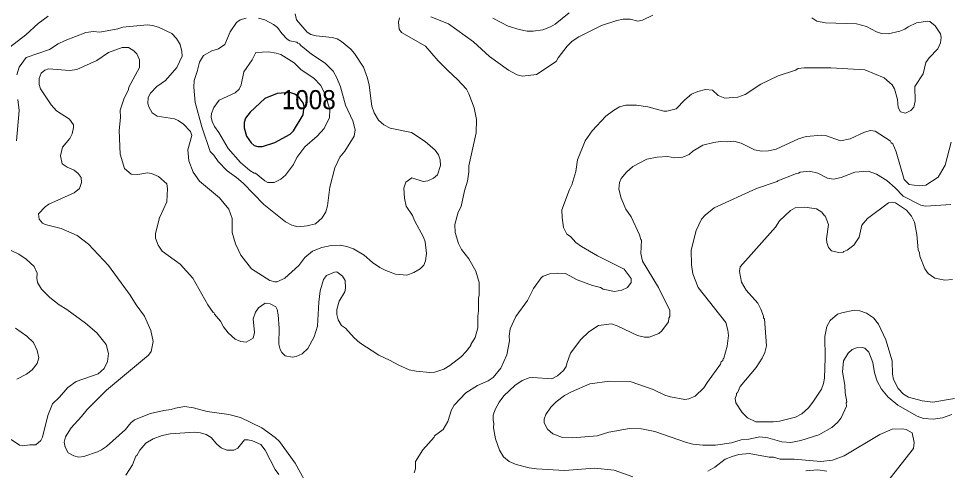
# Model space of a CAD drawing. Extents: x 447.8 to 473.9, y 7733.1 to 7760.8.
# Drawn here: x 456.578 to 460.462, y 7748.586 to 7750.473 of the extents above; entities that cross this region are included whole.
import ezdxf

# ---------------------------------------------------------------- set-up
doc = ezdxf.new("R2010")
doc.units = 0
doc.header["$LTSCALE"] = 0.032
doc.layers.add('1', color=7, linetype='Continuous', lineweight=25)
doc.layers.add('2', color=7, linetype='Continuous', lineweight=13)
doc.layers.add('21', color=7, linetype='Continuous')

msp = doc.modelspace()

# ---------------------------------------------------------------- linework, layer by layer
at = {"layer": '1'}
msp.add_lwpolyline([(457.7136, 7749.9901), (457.7272, 7750.0039), (457.7685, 7750.0716), (457.7728, 7750.1073), (457.7679, 7750.1205), (457.751, 7750.1437), (457.7326, 7750.1574), (457.713, 7750.1645), (457.6597, 7750.1606), (457.6083, 7750.1392), (457.5461, 7750.0824), (457.5274, 7750.0565), (457.5208, 7750.0394), (457.5208, 7750.0167), (457.5316, 7749.9823), (457.5506, 7749.9536), (457.5633, 7749.943), (457.5792, 7749.9394), (457.5975, 7749.9394), (457.6503, 7749.9548)], close=True, dxfattribs=at)
at = {"layer": '2'}
for points in [[(456.523, 7750.3393), (456.608, 7750.4053), (456.6607, 7750.453), (456.7013, 7750.4825)], [(457.7343, 7750.4929), (457.7399, 7750.4672), (457.785, 7750.4162), (457.8007, 7750.4072), (457.8229, 7750.4004), (457.8899, 7750.3947), (457.9101, 7750.3881), (457.9285, 7750.3767), (457.967, 7750.3454), (457.9829, 7750.3271), (458.0208, 7750.2702), (458.0369, 7750.2242), (458.0436, 7750.1945), (458.0549, 7750.1074), (458.0652, 7750.0791), (458.083, 7750.0482), (458.1048, 7750.029), (458.132, 7750.0158), (458.2205, 7749.9971), (458.278, 7749.9592), (458.3194, 7749.9241), (458.3335, 7749.9043), (458.341, 7749.8832), (458.3426, 7749.8596), (458.3297, 7749.8209), (458.3125, 7749.8066), (458.2891, 7749.7958), (458.2702, 7749.7928), (458.2223, 7749.8077), (458.1977, 7749.7895), (458.1896, 7749.7649), (458.1912, 7749.7223), (458.1989, 7749.69), (458.2256, 7749.65), (458.2338, 7749.6297), (458.2712, 7749.5597), (458.2777, 7749.5402), (458.2841, 7749.4921), (458.2801, 7749.4608), (458.272, 7749.4426), (458.2578, 7749.4273), (458.2307, 7749.4121), (458.2022, 7749.4009), (458.1544, 7749.4053), (458.1132, 7749.4201), (458.0884, 7749.4333), (458.0581, 7749.4546), (458.0236, 7749.4848), (457.9789, 7749.5116), (457.9511, 7749.521), (457.9226, 7749.5265), (457.8845, 7749.525), (457.8459, 7749.5162), (457.8067, 7749.5022), (457.7757, 7749.475), (457.75, 7749.4422), (457.6915, 7749.3894), (457.6597, 7749.3735), (457.6497, 7749.3735), (457.6285, 7749.3793), (457.5523, 7749.4273), (457.5071, 7749.4846), (457.4847, 7749.5328), (457.4707, 7749.5796), (457.4713, 7749.638), (457.4575, 7749.6768), (457.4187, 7749.7242), (457.3353, 7749.7933), (457.308, 7749.8317), (457.2902, 7749.8782), (457.2863, 7749.9244), (457.3021, 7749.9852), (457.2964, 7750.0011), (457.2675, 7750.0326), (457.2454, 7750.048), (457.23, 7750.054), (457.1582, 7750.066), (457.1369, 7750.0792), (457.1229, 7750.1039), (457.119, 7750.1184), (457.1194, 7750.144), (457.1294, 7750.1616), (457.1569, 7750.1892), (457.1918, 7750.2147), (457.2395, 7750.2683), (457.262, 7750.3158), (457.2613, 7750.3353), (457.2533, 7750.3642), (457.2386, 7750.3893)], [(458.3022, 7750.4801), (458.3761, 7750.4515), (458.4806, 7750.376), (458.5477, 7750.3152), (458.6263, 7750.2579), (458.663, 7750.2385), (458.6851, 7750.2321), (458.743, 7750.2392), (458.8262, 7750.2935), (458.8343, 7750.3092), (458.8714, 7750.3573), (458.893, 7750.3783), (458.9213, 7750.3972), (459.0149, 7750.4437)], [(458.8803, 7750.497), (458.8214, 7750.4501), (458.8018, 7750.4383), (458.7701, 7750.4266), (458.7295, 7750.4199), (458.7043, 7750.4212), (458.6707, 7750.428), (458.6257, 7750.442), (458.5614, 7750.4748)], [(459.1875, 7750.4667), (459.23, 7750.488)], [(457.2386, 7750.3893), (457.219, 7750.4113), (457.1633, 7750.4369), (457.1383, 7750.4444), (457.1161, 7750.4468), (457.0143, 7750.4372)], [(457.5818, 7750.4747), (457.6075, 7750.4674), (457.6441, 7750.449), (457.6612, 7750.4363), (457.6794, 7750.4107), (457.7016, 7750.3865), (457.7124, 7750.3804), (457.7422, 7750.374), (457.7458, 7750.3698), (457.7528, 7750.368), (457.7579, 7750.3609), (457.8025, 7750.3238), (457.8601, 7750.2864), (457.8935, 7750.2531), (457.9091, 7750.226), (457.924, 7750.1885), (457.9456, 7750.1116), (457.9764, 7750.0465), (457.9858, 7750.0087), (457.9819, 7749.9826), (457.9428, 7749.9188), (457.9209, 7749.8942), (457.901, 7749.85), (457.8802, 7749.7682), (457.8705, 7749.6909), (457.8633, 7749.6652), (457.847, 7749.6402), (457.819, 7749.6159), (457.7854, 7749.6076), (457.7459, 7749.6028), (457.7209, 7749.6098), (457.6948, 7749.6247), (457.6038, 7749.6963), (457.5173, 7749.7852), (457.49, 7749.8093), (457.451, 7749.837), (457.4131, 7749.8766), (457.3941, 7749.9028), (457.3792, 7749.9181), (457.3448, 7750.0204), (457.3169, 7750.1225), (457.3103, 7750.1871), (457.3119, 7750.2139), (457.3254, 7750.252), (457.3345, 7750.2911), (457.351, 7750.3183), (457.3867, 7750.338), (457.4141, 7750.3464), (457.4399, 7750.3643), (457.4622, 7750.4181), (457.4895, 7750.4562), (457.5051, 7750.4681), (457.5291, 7750.4747)], [(457.6541, 7749.2686), (457.6595, 7749.2577), (457.6637, 7749.2352), (457.6676, 7749.1797), (457.6668, 7749.1129), (457.6724, 7749.0901), (457.6789, 7749.0784), (457.6935, 7749.0639), (457.7226, 7749.0585), (457.739, 7749.061), (457.7636, 7749.0725), (457.7871, 7749.0949), (457.8142, 7749.1439), (457.8284, 7749.1879), (457.8329, 7749.2884), (457.8392, 7749.3364), (457.8533, 7749.3836), (457.8651, 7749.3997), (457.8985, 7749.4143), (457.9083, 7749.4149), (457.9329, 7749.3966), (457.943, 7749.379), (457.9457, 7749.3463), (457.9425, 7749.3311), (457.919, 7749.2923), (457.909, 7749.2583), (457.9095, 7749.2371), (457.9144, 7749.2141), (457.9277, 7749.1915), (457.9447, 7749.1801), (457.9816, 7749.1389), (458.0057, 7749.1186), (458.0849, 7749.067), (458.1293, 7749.0464), (458.1676, 7749.0247), (458.2115, 7749.006), (458.2409, 7749), (458.2974, 7748.9944), (458.3189, 7748.9967), (458.3562, 7749.0092), (458.3808, 7749.024), (458.4294, 7749.0619), (458.4484, 7749.0808), (458.4688, 7749.107), (458.4689, 7749.1121), (458.4868, 7749.1411), (458.4989, 7749.1813), (458.4982, 7749.2304), (458.5012, 7749.2522), (458.5013, 7749.3053), (458.5044, 7749.3171), (458.5043, 7749.3708), (458.4902, 7749.4176), (458.4605, 7749.4693), (458.4304, 7749.5091), (458.4177, 7749.5342), (458.404, 7749.579), (458.4019, 7749.6131), (458.4159, 7749.6638), (458.4289, 7749.6888), (458.4429, 7749.754), (458.4549, 7749.7941), (458.4603, 7749.833), (458.4604, 7749.8575), (458.4909, 7749.9957), (458.4925, 7750.0512), (458.4826, 7750.1003), (458.4612, 7750.1588), (458.4507, 7750.1781), (458.4137, 7750.2192), (458.3724, 7750.2557), (458.3328, 7750.2961), (458.2797, 7750.3581), (458.1786, 7750.4154), (458.1696, 7750.429), (458.1664, 7750.4584), (458.171, 7750.476)], [(459.8949, 7750.4767), (459.9162, 7750.4618), (459.9517, 7750.4548), (460.0809, 7750.4514), (460.1239, 7750.4401), (460.165, 7750.4172), (460.1856, 7750.4101), (460.2144, 7750.41), (460.2628, 7750.4206), (460.2836, 7750.4282), (460.2978, 7750.4383), (460.3321, 7750.4555), (460.3798, 7750.4627), (460.3887, 7750.4613), (460.4104, 7750.4429), (460.4327, 7750.4094), (460.4355, 7750.3934), (460.433, 7750.3713), (460.4214, 7750.3471), (460.3848, 7750.3086), (460.3712, 7750.2897), (460.36, 7750.2424), (460.326, 7750.1894), (460.3273, 7750.1285), (460.3215, 7750.103), (460.3083, 7750.0886), (460.2865, 7750.0777), (460.2659, 7750.0829), (460.2554, 7750.1012), (460.2527, 7750.1348), (460.2405, 7750.18), (460.2309, 7750.1958), (460.197, 7750.2256), (460.1168, 7750.2591), (459.9741, 7750.2679), (459.8633, 7750.2673), (459.8383, 7750.2647), (459.8266, 7750.2582), (459.7544, 7750.2339), (459.6819, 7750.1994), (459.6156, 7750.1558), (459.5852, 7750.1442), (459.5309, 7750.1407), (459.5039, 7750.1516), (459.479, 7750.1739), (459.4499, 7750.1766), (459.4188, 7750.169), (459.3914, 7750.1567), (459.3635, 7750.1337), (459.3279, 7750.0961), (459.2889, 7750.0861), (459.2754, 7750.0867), (459.2094, 7750.1045), (459.1621, 7750.1116), (459.1172, 7750.1117), (459.0909, 7750.104), (459.065, 7750.0895), (459.0341, 7750.0656), (458.977, 7750.0045), (458.9466, 7749.9624), (458.9145, 7749.8828), (458.9077, 7749.8338), (458.8913, 7749.7783), (458.881, 7749.759), (458.8502, 7749.6736), (458.8509, 7749.6426), (458.8568, 7749.6011), (458.8706, 7749.572), (458.8852, 7749.5633), (458.9082, 7749.5379), (458.9313, 7749.5215), (458.9987, 7749.4821), (459.1107, 7749.4259), (459.139, 7749.3878), (459.1389, 7749.3705), (459.1246, 7749.3496)], [(459.0149, 7750.4437), (459.0799, 7750.4651), (459.1061, 7750.4708), (459.1358, 7750.47), (459.1668, 7750.463), (459.1875, 7750.4667)], [(457.0143, 7750.4372), (456.9933, 7750.4305), (456.9185, 7750.4165), (456.8909, 7750.4188), (456.8594, 7750.4147), (456.7729, 7750.3817), (456.7441, 7750.3681), (456.7069, 7750.3445), (456.6096, 7750.3102), (456.58, 7750.2697), (456.5705, 7750.2384)], [(456.8096, 7748.6465), (456.7859, 7748.6593), (456.7735, 7748.6831), (456.7685, 7748.7039), (456.775, 7748.7263), (456.7976, 7748.7632), (456.8419, 7748.8114), (456.8645, 7748.8404), (456.9455, 7748.9214), (457.1213, 7749.0669), (457.1321, 7749.0829), (457.1416, 7749.1243), (457.1317, 7749.1703), (457.1045, 7749.2296), (457.0695, 7749.277), (457.045, 7749.318), (456.9541, 7749.4417), (456.8712, 7749.5308), (456.8227, 7749.5673), (456.7561, 7749.596), (456.6892, 7749.6127), (456.6781, 7749.6185), (456.6645, 7749.635), (456.6621, 7749.6572), (456.689, 7749.6866), (456.7044, 7749.6973), (456.811, 7749.7453), (456.8332, 7749.7639), (456.8411, 7749.7887), (456.8392, 7749.8099), (456.8278, 7749.8259), (456.8107, 7749.8405), (456.782, 7749.8523), (456.7611, 7749.8665), (456.7533, 7749.9002), (456.7622, 7749.9362), (456.7921, 7749.9721), (456.8027, 7749.9922), (456.8083, 7750.0178), (456.8081, 7750.0298), (456.7914, 7750.0531), (456.7373, 7750.0873), (456.714, 7750.1123), (456.6705, 7750.1799), (456.6644, 7750.1978), (456.6644, 7750.2227), (456.673, 7750.2451), (456.6881, 7750.2575), (456.7031, 7750.2633), (456.7929, 7750.2569), (456.8218, 7750.2606), (456.9059, 7750.2983), (456.9541, 7750.3319), (457.0115, 7750.352), (457.038, 7750.3522), (457.0601, 7750.3384), (457.0732, 7750.3264), (457.0832, 7750.3011), (457.0839, 7750.2694), (457.0394, 7750.1864), (457.0374, 7750.1763), (457.018, 7750.137), (457.0033, 7750.0899), (457.0039, 7750.0604), (456.9985, 7750.0058), (457.0033, 7749.907), (457.0215, 7749.8467), (457.0495, 7749.8229), (457.0764, 7749.8216), (457.117, 7749.8294), (457.1341, 7749.8261), (457.1636, 7749.8134), (457.1976, 7749.7828), (457.2004, 7749.7637), (457.1977, 7749.7071), (457.1679, 7749.6401), (457.1507, 7749.575), (457.1508, 7749.5559), (457.1612, 7749.527), (457.1785, 7749.5019), (457.2535, 7749.4468), (457.3065, 7749.3891), (457.3693, 7749.2773), (457.3919, 7749.2456), (457.3964, 7749.2441), (457.3974, 7749.2387), (457.4219, 7749.2088), (457.4356, 7749.1853), (457.455, 7749.1599), (457.4836, 7749.1339), (457.508, 7749.1239), (457.5294, 7749.1219), (457.5585, 7749.1375), (457.565, 7749.1625), (457.5588, 7749.2195)], [(456.5751, 7750.1352), (456.5808, 7750.0892), (456.5696, 7749.9629)], [(458.8075, 7748.9679), (458.8317, 7748.981), (458.857, 7749.0037), (458.8679, 7749.0193), (458.87, 7749.0324), (458.8864, 7749.0754), (458.9284, 7749.1327), (458.962, 7749.1647), (459.0035, 7749.1915), (459.0568, 7749.1979), (459.0804, 7749.1898), (459.1653, 7749.1487), (459.1957, 7749.1428), (459.2148, 7749.1426), (459.2554, 7749.1583), (459.2673, 7749.1688), (459.295, 7749.2062), (459.2967, 7749.2218), (459.3005, 7749.2284), (459.3012, 7749.254), (459.2537, 7749.35), (459.1869, 7749.4598), (459.1796, 7749.4912), (459.1826, 7749.5481), (459.1796, 7749.5501), (459.1745, 7749.5694), (459.139, 7749.6451), (459.1177, 7749.6763), (459.0983, 7749.7228), (459.0882, 7749.7602), (459.0906, 7749.7886), (459.0983, 7749.8051), (459.1199, 7749.8317), (459.1465, 7749.8548), (459.2048, 7749.8855), (459.2481, 7749.8937), (459.2914, 7749.8969), (459.3218, 7749.8921), (459.3549, 7749.8947), (459.382, 7749.9056), (459.3978, 7749.9187), (459.4385, 7749.9438), (459.4846, 7749.9558), (459.511, 7749.9594), (459.5409, 7749.9579), (459.5694, 7749.9609), (459.5992, 7749.9525), (459.6556, 7749.9242), (459.6842, 7749.9194), (459.713, 7749.9201), (459.7457, 7749.9275), (459.8397, 7749.9713), (459.8713, 7749.9801), (459.9362, 7749.9858), (459.9514, 7749.9843), (460.0152, 7749.9628), (460.0557, 7749.9704), (460.1147, 7749.9984), (460.1402, 7750.0059), (460.16, 7750.0029), (460.2218, 7749.9622), (460.2265, 7749.9538), (460.2329, 7749.9501), (460.2473, 7749.9166), (460.2811, 7749.8013), (460.3016, 7749.7805), (460.3441, 7749.7743), (460.3719, 7749.7774), (460.4224, 7749.8108), (460.4524, 7749.8608), (460.478, 7749.9571)], [(460.4761, 7749.6965), (460.37, 7749.6893), (460.3504, 7749.6937), (460.2763, 7749.7316), (460.2427, 7749.766), (460.2081, 7749.7963), (460.1657, 7749.823), (460.1301, 7749.8359), (460.0744, 7749.832), (460.0173, 7749.8093), (459.9854, 7749.8024), (459.9607, 7749.8059), (459.9193, 7749.8271), (459.8846, 7749.8359), (459.8457, 7749.832), (459.8389, 7749.8272), (459.8307, 7749.8263), (459.7522, 7749.7951), (459.7502, 7749.792), (459.6639, 7749.7631), (459.4864, 7749.6832), (459.4486, 7749.6522), (459.4331, 7749.6358), (459.4115, 7749.5877), (459.3903, 7749.5062), (459.3912, 7749.445), (459.3975, 7749.4074), (459.4201, 7749.3492), (459.5352, 7749.2036), (459.5443, 7749.1711), (459.5466, 7749.149), (459.5403, 7749.1045), (459.5274, 7749.0547), (459.5238, 7749.052), (459.5221, 7749.0444), (459.5163, 7749.0399), (459.5132, 7749.0299), (459.458, 7748.9545), (459.4437, 7748.9308), (459.4076, 7748.8964), (459.381, 7748.8841), (459.3633, 7748.8813), (459.3039, 7748.8927), (459.2796, 7748.9003), (459.2318, 7748.924), (459.1394, 7748.9558), (459.0489, 7748.959), (458.9665, 7748.9471), (458.89, 7748.9144), (458.861, 7748.8984), (458.8263, 7748.8728), (458.8041, 7748.8506), (458.7829, 7748.819), (458.7757, 7748.8002), (458.7756, 7748.7839), (458.7891, 7748.7579), (458.812, 7748.7392), (458.8526, 7748.7234), (458.8947, 7748.7217), (458.9972, 7748.7304), (459.0467, 7748.7459), (459.1327, 7748.7602), (459.182, 7748.7595), (459.2383, 7748.7487), (459.3715, 7748.7018), (459.3975, 7748.6958), (459.4386, 7748.6914), (459.4925, 7748.6914), (459.5583, 7748.7007), (459.5992, 7748.7137), (459.6321, 7748.7159), (459.678, 7748.7265), (459.7114, 7748.7218), (459.769, 7748.7048), (459.8077, 7748.7029), (459.8489, 7748.7107), (459.9242, 7748.7346), (459.9784, 7748.7648), (460.0015, 7748.7854), (460.0177, 7748.8049), (460.0403, 7748.8536), (460.0389, 7748.8681), (460.0413, 7748.8715), (460.0346, 7748.9097), (460.0331, 7748.9422), (460.0228, 7748.998), (460.0275, 7749.0429)], [(459.5949, 7749.4359), (459.7436, 7749.6017), (459.7595, 7749.6289), (459.8053, 7749.6721), (459.8249, 7749.6826), (459.8652, 7749.686), (459.9137, 7749.678), (459.9364, 7749.6643), (459.9476, 7749.6494), (459.9505, 7749.649), (459.965, 7749.6125), (459.9555, 7749.5534), (459.9572, 7749.5376), (459.9647, 7749.5168), (459.9772, 7749.5023), (460.006, 7749.4962), (460.0264, 7749.497), (460.0285, 7749.5008), (460.0422, 7749.5051), (460.0706, 7749.5272), (460.0921, 7749.5605), (460.1045, 7749.6096), (460.1275, 7749.6378), (460.2149, 7749.7031), (460.2301, 7749.7062), (460.244, 7749.7036), (460.2911, 7749.6727), (460.3109, 7749.6483), (460.3238, 7749.6226), (460.3345, 7749.571), (460.3401, 7749.5072), (460.3449, 7749.494), (460.346, 7749.4801), (460.3672, 7749.4283), (460.3812, 7749.4078), (460.4098, 7749.3893), (460.4503, 7749.3811), (460.4833, 7749.3838)], [(456.4736, 7749.5393), (456.5794, 7749.4896), (456.6093, 7749.468), (456.6431, 7749.4377), (456.656, 7749.409), (456.6546, 7749.3884), (456.6569, 7749.3705), (456.6741, 7749.3435), (456.7093, 7749.3081), (456.7483, 7749.2776), (456.7802, 7749.2579), (456.8579, 7749.2013), (456.9049, 7749.16), (456.9446, 7749.112), (456.9535, 7749.074), (456.9503, 7749.0401), (456.9357, 7749.0112), (456.9105, 7748.9893), (456.8187, 7748.9569), (456.7848, 7748.9321), (456.7498, 7748.8917), (456.7197, 7748.8641), (456.701, 7748.8151), (456.6784, 7748.7239), (456.6717, 7748.7101), (456.6505, 7748.693), (456.6253, 7748.6929), (456.5947, 7748.6881), (456.5818, 7748.6906), (456.5479, 7748.7154)], [(459.6819, 7749.2599), (459.6686, 7749.285), (459.6201, 7749.3393), (459.6012, 7749.3722), (459.5925, 7749.4164), (459.5949, 7749.4359)], [(458.9774, 7749.3586), (458.9136, 7749.3815), (458.8653, 7749.408), (458.8308, 7749.4103), (458.8001, 7749.4064), (458.771, 7749.3967), (458.7626, 7749.39), (458.731, 7749.346), (458.706, 7749.2949), (458.6573, 7749.2288), (458.6329, 7749.1777), (458.6296, 7749.1467), (458.631, 7749.1273), (458.6191, 7749.0691), (458.595, 7749.0128), (458.5619, 7748.9733), (458.542, 7748.9601), (458.497, 7748.9407), (458.4487, 7748.9094), (458.3995, 7748.8581), (458.3884, 7748.8381), (458.3729, 7748.7897), (458.3538, 7748.7573), (458.3176, 7748.73), (458.3156, 7748.7248), (458.2691, 7748.672), (458.2372, 7748.6225), (458.2383, 7748.5918), (458.2321, 7748.5751)], [(459.1246, 7749.3496), (459.1006, 7749.3381), (459.0699, 7749.3326), (459.0225, 7749.343), (459.0106, 7749.3498), (458.9774, 7749.3586)], [(457.5588, 7749.2195), (457.5683, 7749.2467), (457.5819, 7749.265), (457.6092, 7749.2844), (457.6297, 7749.2821), (457.6541, 7749.2686)], [(460.4915, 7748.8856), (460.4011, 7748.8701), (460.3559, 7748.8765), (460.2991, 7748.8915), (460.2782, 7748.904), (460.256, 7748.9279), (460.2367, 7748.965), (460.2328, 7748.9871), (460.2303, 7749.0436), (460.2043, 7749.1318), (460.1736, 7749.1968), (460.1521, 7749.2225), (460.1237, 7749.242), (460.0962, 7749.2517), (460.072, 7749.2548), (460.0199, 7749.2445), (460.0019, 7749.2384), (459.9717, 7749.2126), (459.9576, 7749.1875), (459.9491, 7749.1446), (459.9507, 7749.0555), (459.9474, 7748.971), (459.9441, 7748.9483), (459.9349, 7748.9255), (459.8995, 7748.8703), (459.8806, 7748.8474), (459.8526, 7748.8216), (459.8268, 7748.8085), (459.7601, 7748.7908), (459.7348, 7748.7883), (459.6603, 7748.7884), (459.6262, 7748.8058), (459.603, 7748.8281), (459.5771, 7748.868), (459.574, 7748.8867), (459.5802, 7748.9017), (459.5803, 7748.9089), (459.5834, 7748.9104), (459.5957, 7748.9361), (459.6622, 7749.0162), (459.6871, 7749.0547), (459.6985, 7749.0788), (459.7053, 7749.1057), (459.6971, 7749.2186), (459.6927, 7749.2213), (459.6925, 7749.2295), (459.6819, 7749.2599)], [(456.5714, 7748.9664), (456.611, 7748.9874), (456.6349, 7749.0052), (456.6561, 7749.0321), (456.6633, 7749.056), (456.6566, 7749.0866), (456.6399, 7749.1202), (456.6131, 7749.1471), (456.5652, 7749.1802)], [(460.0275, 7749.0429), (460.0469, 7749.0758), (460.0631, 7749.0914), (460.0817, 7749.0984), (460.1048, 7749.0992), (460.116, 7749.0959)], [(460.116, 7749.0959), (460.1331, 7749.0803), (460.1495, 7749.0365), (460.157, 7748.9937), (460.1685, 7748.9585), (460.1863, 7748.9245), (460.2138, 7748.8919), (460.2549, 7748.8582), (460.3359, 7748.8128), (460.3612, 7748.8032), (460.4023, 7748.7996), (460.4412, 7748.8048), (460.4796, 7748.8195)], [(458.6077, 7748.8971), (458.6526, 7748.9404), (458.6844, 7748.9616), (458.7129, 7748.9726), (458.7278, 7748.9742), (458.8075, 7748.9679)], [(459.1471, 7748.5592), (459.068, 7748.587), (458.9857, 7748.5952), (458.8612, 7748.5856), (458.7437, 7748.5921), (458.7129, 7748.5966), (458.6581, 7748.6104), (458.6297, 7748.6236), (458.6058, 7748.6424), (458.5892, 7748.6704), (458.572, 7748.7174), (458.5632, 7748.7636), (458.5653, 7748.7822), (458.5623, 7748.796), (458.5631, 7748.816), (458.5713, 7748.8399), (458.5877, 7748.8704), (458.6077, 7748.8971)], [(457.7876, 7748.5199), (457.7348, 7748.6156), (457.6692, 7748.706), (457.6514, 7748.7234), (457.5952, 7748.7639), (457.5061, 7748.8073), (457.4579, 7748.8194), (457.3664, 7748.8316), (457.31, 7748.8476), (457.2722, 7748.8524), (457.2338, 7748.846), (457.2168, 7748.8396), (457.1851, 7748.8361), (457.1291, 7748.8234), (457.0631, 7748.7966), (457.047, 7748.7847), (457.025, 7748.7573), (456.9464, 7748.6857)], [(457.0264, 7748.5654), (457.0544, 7748.6085), (457.0685, 7748.6449), (457.0728, 7748.6482), (457.085, 7748.6706), (457.1104, 7748.6999), (457.1408, 7748.718), (457.1788, 7748.7318), (457.2127, 7748.7387), (457.3142, 7748.7451), (457.3387, 7748.7427), (457.3625, 7748.7357), (457.3837, 7748.7233), (457.4073, 7748.6953), (457.4251, 7748.6804), (457.4486, 7748.6707), (457.4776, 7748.6706), (457.4953, 7748.6786), (457.5233, 7748.7129), (457.5375, 7748.7138), (457.5565, 7748.7099), (457.5906, 7748.6937), (457.6088, 7748.6698), (457.6513, 7748.5901), (457.6666, 7748.5681)], [(460.2225, 7748.5529), (460.3194, 7748.6768), (460.3225, 7748.7021), (460.3143, 7748.742), (460.2886, 7748.7563), (460.2744, 7748.7594), (460.2305, 7748.7576), (460.1797, 7748.7362), (460.0298, 7748.6468), (459.9807, 7748.6288), (459.9321, 7748.6232), (459.8211, 7748.6328), (459.763, 7748.6321), (459.7349, 7748.6407), (459.7165, 7748.6413), (459.6332, 7748.6568), (459.5892, 7748.6519), (459.5623, 7748.6445), (459.5323, 7748.632), (459.4892, 7748.5994), (459.46, 7748.5823)], [(456.9464, 7748.6857), (456.9256, 7748.6713), (456.9076, 7748.6629), (456.8504, 7748.6445), (456.8298, 7748.6417), (456.8096, 7748.6465)], [(459.8698, 7748.5846), (459.9196, 7748.588), (459.9569, 7748.5825)]]:
    msp.add_lwpolyline(points, dxfattribs=at)
msp.add_lwpolyline([(457.5695, 7750.3312), (457.6233, 7750.3345), (457.6546, 7750.329), (457.6744, 7750.3224), (457.7309, 7750.2887), (457.7594, 7750.2592), (457.8123, 7750.2245), (457.8414, 7750.1929), (457.8597, 7750.1553), (457.8801, 7750.0932), (457.8776, 7750.0593), (457.8561, 7750.0137), (457.8262, 7749.9816), (457.7755, 7749.938), (457.7421, 7749.8927), (457.727, 7749.8641), (457.6939, 7749.8189), (457.6747, 7749.803), (457.6473, 7749.7887), (457.6202, 7749.7887), (457.6075, 7749.7957), (457.5689, 7749.8267), (457.5626, 7749.8273), (457.5445, 7749.8387), (457.5054, 7749.8725), (457.4541, 7749.9311), (457.416, 7749.9971), (457.398, 7750.0217), (457.3879, 7750.0432), (457.3832, 7750.0612), (457.3855, 7750.0769), (457.3945, 7750.1016), (457.4174, 7750.1323), (457.4831, 7750.163), (457.5008, 7750.1788), (457.5083, 7750.1962), (457.5198, 7750.2511), (457.555, 7750.3001)], close=True, dxfattribs=at)

# ---------------------------------------------------------------- texts
at = {"layer": '21', "width": 0.95}
msp.add_text('1008', height=0.08, dxfattribs=at).set_placement((457.6782, 7750.0944))

doc.saveas('drawing.dxf')
